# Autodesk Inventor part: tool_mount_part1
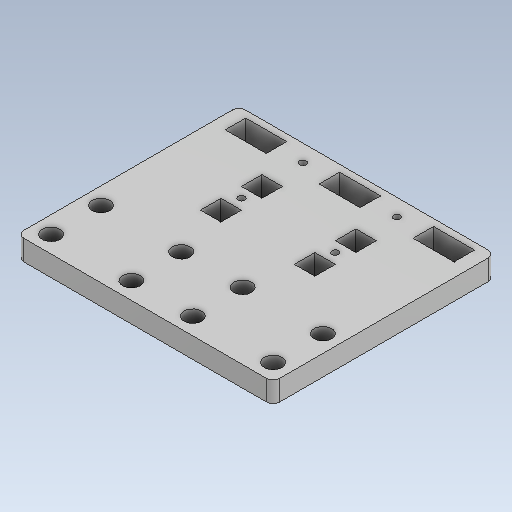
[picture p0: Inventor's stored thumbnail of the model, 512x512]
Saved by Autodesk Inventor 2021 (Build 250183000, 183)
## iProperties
Created: 2026-10
Part Number: tool_mount_part1
Material: Steel
Document SubType Name: Modeling
Designer: hp
Density: 7.85 g/cm^3
Appearance: Default
Author: hp
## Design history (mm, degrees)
feature "Body1"
body "Solid1"
